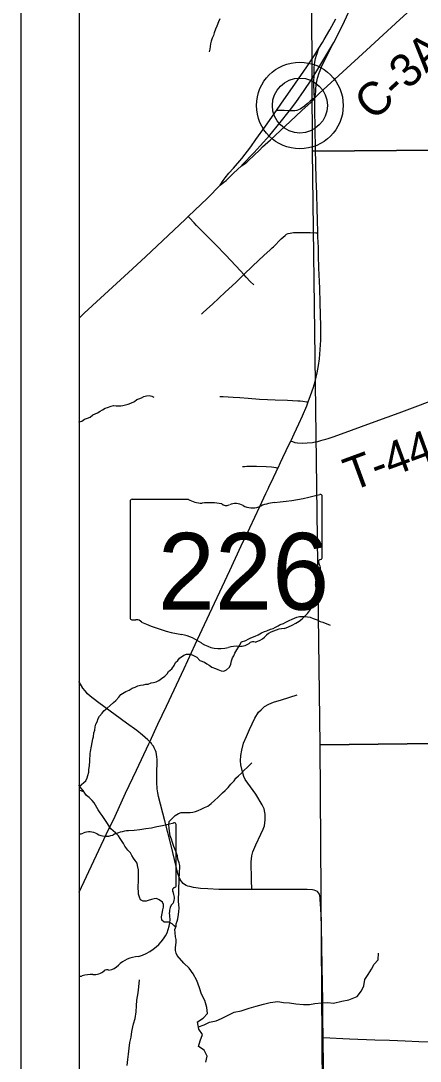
# Model space of a CAD drawing. Extents: x 0 to 34, y 0 to 22.
# Drawn here: x 17.758 to 18.444, y 10.029 to 11.815 of the extents above; entities that cross this region are included whole.
import ezdxf

# ---------------------------------------------------------------- set-up
doc = ezdxf.new("R2010")
doc.units = 0
for name, color, linetype in [('GM_X_County_Road', 7, 'Continuous'), ('GM_X_County_Road_Text', 7, 'Continuous'), ('GM_X_Interchange_Ramps', 7, 'Continuous'), ('GM_X_Major_River_Text', 7, 'Continuous'), ('GM_X_Minor_River', 7, 'Continuous'), ('GM_X_Section', 7, 'Continuous'), ('GM_X_State_Route', 7, 'Continuous'), ('GM_X_State_Shield', 7, 'Continuous'), ('GM_X_Township_Road', 7, 'Continuous'), ('GM_X_Township_Road_Text', 7, 'Continuous'), ('GM_X_Unincorporated', 7, 'Continuous'), ('GM_X_Unincorporated_Location', 7, 'Continuous'), ('SH_Data', 7, 'Continuous')]:
    doc.layers.add(name, color=color, linetype=linetype)

msp = doc.modelspace()

# ---------------------------------------------------------------- linework, layer by layer
at = {"layer": 'GM_X_County_Road'}
msp.add_lwpolyline([(18.2625, 11.683), (18.2699, 11.6903), (18.3514, 11.7649), (18.4086, 11.8174), (18.4384, 11.8446), (18.5022, 11.9035), (18.5117, 11.9129), (18.5242, 11.9253), (18.5401, 11.9425), (18.5514, 11.9551), (18.6473, 12.061), (18.7036, 12.1231), (18.7171, 12.1378)], dxfattribs=at)
at = {"layer": 'GM_X_Interchange_Ramps'}
for points in [[(18.1365, 11.5663), (18.1411, 11.5689), (18.1438, 11.571), (18.1457, 11.5726), (18.1481, 11.5749), (18.1684, 11.5939), (18.173, 11.5986), (18.1866, 11.611), (18.2202, 11.6425), (18.2404, 11.6614), (18.2564, 11.6754), (18.2587, 11.6776), (18.2602, 11.6795), (18.2625, 11.683)], [(18.2625, 11.683), (18.2581, 11.6801), (18.2548, 11.6773), (18.2494, 11.6729), (18.2449, 11.6688), (18.2425, 11.6669), (18.24, 11.6651), (18.2373, 11.6637), (18.2345, 11.6624), (18.2315, 11.6615), (18.2285, 11.6609), (18.2255, 11.6607), (18.2194, 11.6609), (18.2102, 11.6614), (18.2039, 11.6615), (18.1967, 11.6613)]]:
    msp.add_lwpolyline(points, dxfattribs=at)
at = {"layer": 'GM_X_Major_River_Text'}
msp.add_line((17.8579, 10.4195), (17.8579, 10.1742), dxfattribs=at)
msp.add_lwpolyline([(18.0245, 10.3301), (18.0245, 10.3301), (18.0245, 10.3301), (18.0245, 10.435)], dxfattribs=at)
for centre, major_axis, start_param, end_param in [((17.9071, 10.7027), (0.3495, 0), 4.814394, 5.042369), ((18.0208, 10.4352), (0.00367, 0), 6.197627, 7.989034), ((17.8601, 10.4278), (0.0107, 0), 4.502603, 5.185415), ((17.8758, 10.4047), (0.0222, 0), 0.950623, 2.079405), ((17.9045, 10.4364), (0.0267, 0), 4.08156, 5.145723), ((17.9517, 10.3687), (0.0703, 0), 1.699012, 2.107814), ((18.0237, 10.3224), (0.00568, 0), 1.883978, 3.671073), ((18.0206, 10.3297), (0.00393, 0), 5.05454, 6.418171), ((17.9875, 10.3092), (0.0341, 0), 5.934695, 6.695948), ((18.0376, 10.2863), (0.0248, 0), 2.387724, 3.262537), ((17.9267, 10.273), (0.0874, 0), 5.101753, 6.440018), ((17.9635, 10.1701), (0.0479, 0), 1.647645, 2.488434), ((17.8819, 10.1987), (0.0267, 0), 4.691044, 5.507374), ((17.9061, 10.1794), (0.00752, 0), 1.147584, 2.315152), ((17.9029, 10.2069), (0.0282, 0), 4.937069, 5.64225), ((17.8493, 10.2137), (0.0501, 0), 4.884715, 4.996735), ((17.8783, 10.1445), (0.0412, 0), 1.495662, 1.94098)]:
    msp.add_ellipse(centre, major_axis=major_axis, ratio=0.8, start_param=start_param, end_param=end_param, dxfattribs=at)
at = {"layer": 'GM_X_Minor_River'}
msp.add_line((17.8661, 10.4914), (17.8579, 10.4943), dxfattribs=at)
for points in [[(18.0993, 11.8187), (18.0974, 11.8137), (18.0945, 11.8061), (18.0919, 11.8011), (18.0901, 11.7946), (18.0886, 11.7901), (18.0864, 11.7855), (18.0849, 11.7805), (18.0838, 11.7756), (18.0828, 11.7714), (18.0824, 11.7664), (18.0814, 11.7619)], [(17.8579, 11.1263), (17.858, 11.1264), (17.8626, 11.128), (17.8675, 11.1311), (17.8724, 11.1327), (17.8769, 11.1346), (17.8818, 11.1389), (17.8898, 11.142), (17.8943, 11.1447), (17.8981, 11.1471), (17.903, 11.1498), (17.9068, 11.1514), (17.9128, 11.1537), (17.917, 11.1546), (17.9215, 11.1542), (17.9295, 11.1543), (17.9333, 11.1548), (17.9375, 11.1556), (17.942, 11.1568), (17.947, 11.1584), (17.953, 11.1615), (17.9568, 11.165), (17.9606, 11.1661), (17.9651, 11.1681), (17.9693, 11.1701), (17.9738, 11.1713), (17.9784, 11.1717), (17.9826, 11.1706), (17.9864, 11.1692)], [(17.8589, 10.5012), (17.8698, 10.5101), (17.8717, 10.515), (17.8731, 10.5192), (17.8746, 10.5249), (17.8749, 10.5295), (17.8756, 10.536), (17.8762, 10.5447), (17.8768, 10.5569), (17.8775, 10.5607), (17.8793, 10.5694), (17.8814, 10.582), (17.8825, 10.5858), (17.8832, 10.5923), (17.885, 10.5972), (17.8854, 10.603), (17.8868, 10.6075), (17.8891, 10.6114), (17.8909, 10.6171), (17.8931, 10.6213), (17.8976, 10.6263), (17.9006, 10.6305), (17.9062, 10.6351), (17.9111, 10.6394), (17.9168, 10.6444), (17.9209, 10.6482), (17.9261, 10.654), (17.9295, 10.6582), (17.9382, 10.6633), (17.9439, 10.6656), (17.9492, 10.6691), (17.9545, 10.6707), (17.959, 10.6731), (17.9635, 10.6746), (17.9688, 10.6751), (17.9726, 10.6759), (17.9768, 10.6763), (17.9817, 10.6783), (17.9855, 10.6787), (17.9905, 10.6799), (17.995, 10.6823), (17.9995, 10.6861), (18.0052, 10.6896), (18.0089, 10.6939), (18.0115, 10.6977), (18.0172, 10.7023), (18.0209, 10.7081), (18.0235, 10.7131), (18.0276, 10.7169), (18.0302, 10.7207), (18.0378, 10.7258), (18.0423, 10.7274), (18.0484, 10.7274), (18.0522, 10.7264), (18.0603, 10.7223), (18.0653, 10.717), (18.0733, 10.7137), (18.0772, 10.7111), (18.081, 10.7089), (18.0856, 10.7055), (18.0921, 10.7033), (18.0963, 10.7015), (18.1016, 10.6993), (18.1066, 10.6986), (18.1108, 10.7005), (18.116, 10.7052), (18.1186, 10.7105), (18.1197, 10.7162), (18.1215, 10.7212), (18.1234, 10.725), (18.1252, 10.7292), (18.1289, 10.735), (18.1315, 10.7399), (18.1338, 10.7438), (18.1368, 10.7488), (18.1443, 10.7511), (18.1485, 10.7535), (18.153, 10.7558), (18.1602, 10.7586), (18.1655, 10.7609), (18.1712, 10.764), (18.1765, 10.7664), (18.1802, 10.7679), (18.1863, 10.7703), (18.1912, 10.7719), (18.1954, 10.7738), (18.1995, 10.7762), (18.2033, 10.7785), (18.209, 10.7801), (18.2128, 10.7824), (18.2188, 10.7852), (18.2237, 10.7879), (18.2275, 10.7895), (18.2317, 10.7914), (18.2362, 10.7922), (18.2461, 10.7924), (18.2499, 10.7917), (18.2549, 10.791), (18.2598, 10.7888), (18.2667, 10.7866), (18.2717, 10.7836)], [(18.2717, 10.7836), (18.2763, 10.7825), (18.2805, 10.7807), (18.2851, 10.7792), (18.2889, 10.7774)], [(18.0265, 10.2103), (18.0247, 10.2139), (18.0235, 10.2185), (18.0234, 10.2234), (18.0241, 10.2284), (18.0244, 10.2325), (18.0244, 10.2379), (18.0235, 10.2424), (18.0231, 10.2492), (18.0226, 10.2549), (18.0244, 10.2603), (18.0248, 10.2645), (18.0266, 10.269), (18.0277, 10.2732), (18.0287, 10.2805), (18.0294, 10.2858), (18.0297, 10.2915), (18.0293, 10.2979), (18.0288, 10.3029), (18.0288, 10.309), (18.029, 10.3166), (18.0293, 10.3276), (18.0295, 10.3359), (18.0298, 10.3435), (18.0301, 10.3492), (18.0304, 10.3546), (18.0308, 10.3603), (18.0307, 10.3648), (18.0299, 10.3694), (18.0275, 10.3758), (18.0267, 10.3811), (18.0235, 10.3906), (18.0208, 10.3974), (18.0184, 10.4042), (18.0168, 10.4098), (18.0144, 10.4159), (18.0136, 10.4197), (18.0132, 10.4238), (18.0127, 10.4288), (18.0123, 10.4345), (18.0126, 10.4402), (18.0175, 10.4456), (18.0227, 10.4506), (18.0284, 10.4541), (18.0333, 10.456), (18.0413, 10.4557), (18.0485, 10.4558), (18.0535, 10.4563), (18.0576, 10.4575), (18.0622, 10.4591), (18.0675, 10.4614), (18.0735, 10.4642), (18.0788, 10.4669), (18.0848, 10.4711), (18.0905, 10.4762), (18.0965, 10.4823), (18.1002, 10.4854), (18.1044, 10.4893), (18.1089, 10.4935), (18.1138, 10.4989), (18.1183, 10.5043), (18.1239, 10.5104), (18.1269, 10.5146), (18.1314, 10.5189), (18.1366, 10.5235), (18.1415, 10.5285), (18.1464, 10.5331), (18.1509, 10.5377), (18.1547, 10.5412)], [(18.0239, 10.2586), (18.0214, 10.2614), (18.0175, 10.2644), (18.0126, 10.2673), (18.0084, 10.2677), (18.0038, 10.2672), (18, 10.271), (17.9995, 10.2767), (18.0006, 10.2824), (18.002, 10.2888), (18.0027, 10.2934), (18.003, 10.298), (18.0011, 10.3017), (17.9953, 10.3059), (17.9911, 10.3081), (17.9869, 10.3073), (17.982, 10.3064), (17.9767, 10.3048), (17.9729, 10.3037), (17.968, 10.3036), (17.9634, 10.3058), (17.9614, 10.3103), (17.9602, 10.3153), (17.9598, 10.3202), (17.9593, 10.3255), (17.9596, 10.3301), (17.9599, 10.3361), (17.9598, 10.3479), (17.9597, 10.3574), (17.9584, 10.365), (17.9576, 10.3688), (17.9541, 10.3733), (17.9514, 10.3774), (17.9483, 10.382), (17.9464, 10.3865), (17.9417, 10.391), (17.9367, 10.3978), (17.934, 10.4023), (17.932, 10.406), (17.9285, 10.4113), (17.9258, 10.4158), (17.9204, 10.4207), (17.9166, 10.4245), (17.9127, 10.4278), (17.9093, 10.4323), (17.9054, 10.4387), (17.8976, 10.4508), (17.8941, 10.4553), (17.8906, 10.4606), (17.886, 10.4681), (17.8836, 10.4723), (17.8805, 10.4764), (17.8751, 10.4816), (17.8709, 10.485), (17.8678, 10.4891), (17.8647, 10.4933), (17.8612, 10.4982), (17.8581, 10.5023), (17.8579, 10.5027)], [(18.0775, 10.121), (18.0737, 10.1327), (18.0681, 10.1438), (18.0647, 10.1544), (18.0602, 10.167), (18.0539, 10.1788), (18.0467, 10.1887), (18.0377, 10.1971), (18.0265, 10.2103)], [(18.0629, 10.0879), (18.0724, 10.0914), (18.0819, 10.0955), (18.0933, 10.0981), (18.1027, 10.1019), (18.1114, 10.1068), (18.1243, 10.1128), (18.1361, 10.1154), (18.1497, 10.1195), (18.1622, 10.1232), (18.1743, 10.1266), (18.186, 10.1295), (18.1993, 10.131), (18.2087, 10.1294), (18.2189, 10.129), (18.2299, 10.1274), (18.2431, 10.1262), (18.2533, 10.1262), (18.2628, 10.1277), (18.2749, 10.1291), (18.2847, 10.1294), (18.2945, 10.1286), (18.3089, 10.1316), (18.321, 10.1342), (18.3354, 10.1398), (18.3426, 10.1493), (18.3465, 10.158), (18.3484, 10.169), (18.3541, 10.1773), (18.3598, 10.1868), (18.3648, 10.1955), (18.3712, 10.203), (18.372, 10.214)], [(17.9406, 10.0211), (17.9418, 10.0313), (17.9425, 10.0408), (17.9441, 10.051), (17.9453, 10.0605), (17.9472, 10.07), (17.9487, 10.0795), (17.9511, 10.0927), (17.9545, 10.1022), (17.9557, 10.1132), (17.9565, 10.1238), (17.9573, 10.1333), (17.9592, 10.1458), (17.9604, 10.1564), (17.9616, 10.1686)], [(18.0756, 10.0269), (18.0779, 10.0375), (18.0726, 10.0478), (18.0628, 10.0539), (18.0659, 10.0634), (18.0697, 10.0743), (18.0637, 10.0835), (18.0615, 10.096), (18.071, 10.1024), (18.0786, 10.1103), (18.0775, 10.121)]]:
    msp.add_lwpolyline(points, dxfattribs=at)
at = {"layer": 'GM_X_Section'}
for points in [[(18.2539, 12.6075), (19.256, 12.6012), (19.2699, 11.5992), (18.2587, 11.5914)], [(19.2699, 11.5992), (19.2682, 10.5835), (18.2719, 10.572), (18.2587, 11.5914)], [(18.2719, 10.572), (19.2682, 10.5835), (19.2682, 10.2871), (19.2823, 9.5962), (18.8511, 9.5674), (18.2785, 9.5574)]]:
    msp.add_lwpolyline(points, close=True, dxfattribs=at)
at = {"layer": 'GM_X_State_Route'}
for points in [[(18.2919, 11.7723), (18.2952, 11.7783), (18.3039, 11.7948), (18.3134, 11.8147), (18.3234, 11.8359), (18.329, 11.8487), (18.3347, 11.8617), (18.3476, 11.8956), (18.3633, 11.9362), (18.3748, 11.9663), (18.392, 12.0089), (18.3944, 12.0148), (18.4157, 12.0701), (18.4506, 12.1598), (18.4686, 12.2061), (18.4736, 12.2191), (18.4793, 12.234), (18.4858, 12.251), (18.4879, 12.2563)], [(18.2787, 11.7834), (18.2882, 11.7998), (18.2987, 11.8189)], [(18.0999, 11.5331), (18.1055, 11.5411), (18.1089, 11.5459), (18.1152, 11.5534), (18.1228, 11.5621), (18.1372, 11.5791), (18.1526, 11.5987), (18.1616, 11.6114), (18.1778, 11.6342), (18.1967, 11.6613), (18.2045, 11.6724), (18.2296, 11.708), (18.249, 11.7362), (18.2627, 11.757), (18.2694, 11.768), (18.2757, 11.7783), (18.2787, 11.7834)], [(18.2625, 11.683), (18.2619, 11.6856), (18.2616, 11.688), (18.2612, 11.7103), (18.2613, 11.7221), (18.2613, 11.7227), (18.2618, 11.735), (18.2628, 11.7443), (18.2639, 11.7504), (18.2656, 11.7565), (18.2666, 11.7594), (18.2694, 11.768)], [(18.2613, 11.7221), (18.2659, 11.7294), (18.2919, 11.7723)], [(18.2625, 11.683), (18.2633, 11.686), (18.2636, 11.6889), (18.2643, 11.6942), (18.2646, 11.6986), (18.2652, 11.7047), (18.2661, 11.7109), (18.2675, 11.7169), (18.2702, 11.7258), (18.2707, 11.7272), (18.2754, 11.7392), (18.279, 11.7464), (18.2832, 11.7544), (18.2919, 11.7723)], [(18.0999, 11.5331), (18.1065, 11.5383), (18.1103, 11.5413), (18.1163, 11.5468), (18.1233, 11.5536), (18.1365, 11.5663), (18.1376, 11.5674), (18.1583, 11.589), (18.1689, 11.6003), (18.1853, 11.619), (18.2033, 11.6405), (18.2188, 11.66), (18.2194, 11.6609), (18.2299, 11.675), (18.2441, 11.6954), (18.2561, 11.7136), (18.2613, 11.7221)], [(18.1918, 11.0311), (18.1962, 11.0407), (18.1993, 11.0472), (18.1996, 11.0479), (18.204, 11.057), (18.2078, 11.0651), (18.2135, 11.0772), (18.2187, 11.0881), (18.2213, 11.0934), (18.2219, 11.0948), (18.227, 11.1058), (18.2351, 11.1232), (18.2413, 11.137), (18.2487, 11.1541), (18.2513, 11.1607), (18.2555, 11.1717), (18.2602, 11.1862), (18.263, 11.1957), (18.2667, 11.211), (18.269, 11.2232), (18.2704, 11.235), (18.2721, 11.2511), (18.2728, 11.2668), (18.2728, 11.2911), (18.2718, 11.3307), (18.271, 11.3564), (18.2698, 11.3906), (18.2688, 11.4124), (18.2687, 11.4261), (18.268, 11.4442), (18.2678, 11.4513), (18.2671, 11.474), (18.2665, 11.4919), (18.2661, 11.5179), (18.2652, 11.544), (18.264, 11.5955), (18.2631, 11.6297), (18.2627, 11.6639), (18.2625, 11.683)], [(17.8579, 11.3047), (17.8669, 11.313), (17.8947, 11.3387), (17.9495, 11.3894), (17.9723, 11.4104), (18.0401, 11.4743), (18.0452, 11.4792), (18.0782, 11.5109), (18.0999, 11.5331)], [(17.8579, 10.3189), (17.9047, 10.4181), (17.9197, 10.4497), (17.9377, 10.4892), (17.9563, 10.5286), (17.9775, 10.5735), (17.9792, 10.5772), (17.993, 10.6074), (18.0078, 10.6382), (18.0381, 10.7032), (18.0572, 10.7444), (18.0732, 10.7788), (18.1168, 10.8715), (18.1364, 10.9138), (18.1512, 10.9445), (18.1683, 10.9812), (18.1788, 11.0034), (18.1826, 11.0116), (18.185, 11.017), (18.1893, 11.0259), (18.1918, 11.0311)]]:
    msp.add_lwpolyline(points, dxfattribs=at)
at = {"layer": 'GM_X_State_Shield'}
for p, q in [((17.9458, 10.99), (17.9458, 10.7899)), ((18.0455, 10.9935), (17.949, 10.9935)), ((18.2753, 10.8937), (18.2753, 10.9984)), ((18.2753, 10.8938), (18.2753, 10.8937))]:
    msp.add_line(p, q, dxfattribs=at)
for centre, major_axis, start_param, end_param in [((17.9495, 10.9905), (0.00382, 0), 1.712693, 3.28349), ((18.0685, 11.0167), (0.037, 0), 4.042523, 4.731795), ((18.0808, 10.8811), (0.133, 0), 1.404758, 1.657858), ((18.2025, 10.9323), (0.0703, 0), 1.699011, 2.107814), ((18.1579, 11.2663), (0.3495, 0), 4.814394, 5.042369), ((18.2717, 10.9989), (0.00367, 0), 6.141152, 7.989035), ((18.111, 10.9915), (0.0107, 0), 3.836095, 5.185415), ((18.1267, 10.9684), (0.0222, 0), 0.950623, 2.079405), ((18.1553, 11.0001), (0.0267, 0), 4.081561, 5.145723), ((18.2745, 10.8861), (0.00568, 0), 1.883978, 3.671073), ((18.2384, 10.8728), (0.0341, 0), 5.934695, 6.695948), ((18.2714, 10.8933), (0.00393, 0), 5.05454, 6.418171), ((18.2885, 10.8499), (0.0248, 0), 2.387724, 3.262537), ((18.1775, 10.8366), (0.0874, 0), 5.101752, 6.440018), ((17.9496, 10.7895), (0.00385, 0), 3.00124, 4.508301), ((17.9501, 10.8099), (0.0294, 0), 4.665946, 4.897461), ((17.9562, 10.7784), (0.0106, 0), 0.519207, 1.627899), ((18.09, 10.9582), (0.2524, 0), 4.195997, 4.488961), ((18.0147, 10.7), (0.079, 0), 0.823519, 1.323587), ((18.1537, 10.7705), (0.0282, 0), 4.937069, 5.64225), ((18.2144, 10.7337), (0.0479, 0), 1.647645, 2.488434), ((18.1001, 10.7774), (0.0501, 0), 4.026481, 4.996735), ((18.1291, 10.7082), (0.0412, 0), 1.495662, 1.94098), ((18.1328, 10.7624), (0.0267, 0), 4.691044, 5.507374), ((18.1569, 10.743), (0.00752, 0), 1.147584, 2.315152)]:
    msp.add_ellipse(centre, major_axis=major_axis, ratio=0.8, start_param=start_param, end_param=end_param, dxfattribs=at)
at = {"layer": 'GM_X_Township_Road'}
for points in [[(18.1578, 11.3616), (18.1514, 11.3678), (18.145, 11.3748), (18.1408, 11.3794), (18.1348, 11.386), (18.1096, 11.4126), (18.0921, 11.4312), (18.0706, 11.4529), (18.0596, 11.4636), (18.0553, 11.4681), (18.0474, 11.4767), (18.0452, 11.4792)], [(18.068, 11.3116), (18.0704, 11.3137), (18.0773, 11.3201), (18.0869, 11.3289), (18.1089, 11.3492), (18.127, 11.366), (18.1408, 11.3794), (18.1556, 11.3939), (18.1759, 11.4126), (18.1853, 11.4213), (18.1897, 11.4253), (18.1919, 11.4274), (18.2049, 11.4406), (18.2118, 11.4468), (18.2143, 11.4486), (18.2171, 11.4499), (18.2201, 11.4508), (18.2231, 11.4513), (18.2262, 11.4515), (18.2323, 11.4516), (18.2478, 11.4517), (18.2545, 11.4516), (18.2642, 11.4514), (18.2678, 11.4513)], [(18.2213, 11.0934), (18.2243, 11.0926), (18.2284, 11.0914), (18.2327, 11.0908), (18.2409, 11.0901), (18.2493, 11.0904), (18.2585, 11.0914), (18.2631, 11.0921), (18.2677, 11.0931), (18.273, 11.0944), (18.2769, 11.0955), (18.2816, 11.0968), (18.2857, 11.0982), (18.2939, 11.101), (18.3019, 11.1039), (18.3663, 11.1273), (18.4074, 11.1421), (18.4395, 11.1542), (18.4774, 11.1683), (18.4979, 11.1757), (18.5243, 11.1853), (18.5564, 11.1972), (18.5739, 11.2038), (18.5982, 11.214)], [(18.0995, 11.1702), (18.1051, 11.17), (18.1226, 11.169), (18.1339, 11.1685), (18.1483, 11.1673), (18.1679, 11.1658), (18.1816, 11.1649), (18.1947, 11.1645), (18.2159, 11.1639), (18.2244, 11.1634), (18.2333, 11.1628), (18.2375, 11.1624), (18.2418, 11.1621), (18.2482, 11.1612), (18.2513, 11.1607)], [(18.1383, 11.0497), (18.1419, 11.0499), (18.1462, 11.0502), (18.1492, 11.0505), (18.1539, 11.0507), (18.158, 11.0507), (18.1628, 11.0507), (18.1794, 11.05), (18.1885, 11.0495), (18.1924, 11.0489), (18.1955, 11.0482), (18.1993, 11.0472)], [(17.9792, 10.5772), (17.9758, 10.5804), (17.9666, 10.5886), (17.9571, 10.5964), (17.9396, 10.6092), (17.8919, 10.644), (17.8819, 10.6514), (17.8771, 10.6554), (17.8725, 10.6597), (17.8683, 10.6644), (17.8646, 10.6695), (17.8581, 10.6802), (17.8579, 10.6806)], [(18.1544, 10.3233), (18.1538, 10.3403), (18.1531, 10.3708), (18.1538, 10.3761), (18.1546, 10.3814), (18.1564, 10.3882), (18.1613, 10.4004), (18.1699, 10.4187), (18.1741, 10.4271), (18.1761, 10.4331), (18.1769, 10.4381), (18.1776, 10.4432), (18.1776, 10.4485), (18.1774, 10.4529), (18.1767, 10.456), (18.1756, 10.462), (18.1725, 10.4691), (18.1615, 10.487), (18.1429, 10.5126), (18.1409, 10.5176), (18.1379, 10.5276), (18.1356, 10.5377), (18.135, 10.5444), (18.1356, 10.5539), (18.1372, 10.5627), (18.1401, 10.5748), (18.1451, 10.5861), (18.1504, 10.598), (18.1595, 10.6175), (18.1661, 10.6278), (18.1703, 10.632), (18.1765, 10.638), (18.1836, 10.6418), (18.1915, 10.6453), (18.2052, 10.6495), (18.2321, 10.6579)], [(18.2769, 10.0693), (18.2764, 10.1019), (18.2763, 10.133), (18.276, 10.1609), (18.2755, 10.1919), (18.2747, 10.226), (18.274, 10.2601), (18.2734, 10.2787), (18.2728, 10.2911), (18.2721, 10.3066), (18.2718, 10.3096), (18.2712, 10.3125), (18.2704, 10.3153), (18.2689, 10.3178), (18.267, 10.3199), (18.2645, 10.3215), (18.2617, 10.3225), (18.2588, 10.3231), (18.2496, 10.3236), (18.2342, 10.3236), (18.2031, 10.3234), (18.1659, 10.3233), (18.1544, 10.3233), (18.1287, 10.3234), (18.0976, 10.3238), (18.079, 10.3246), (18.0666, 10.3255), (18.0541, 10.3271), (18.048, 10.3284), (18.0449, 10.3294), (18.042, 10.3306), (18.0392, 10.3322), (18.0366, 10.3341), (18.0344, 10.3365), (18.0325, 10.3391), (18.0309, 10.3419), (18.0296, 10.3448), (18.0277, 10.3508), (18.0217, 10.375), (18.0158, 10.3991), (18.0049, 10.4412), (17.9944, 10.4834), (17.9932, 10.4898), (17.9926, 10.493), (17.9922, 10.4961), (17.9918, 10.4995), (17.9914, 10.505), (17.9912, 10.5109), (17.9913, 10.5257), (17.9919, 10.541), (17.9919, 10.5467), (17.9917, 10.5513), (17.9911, 10.5556), (17.9903, 10.5592), (17.9891, 10.5624), (17.9881, 10.5644), (17.987, 10.567), (17.9855, 10.5694), (17.9836, 10.572), (17.9822, 10.574), (17.9802, 10.5762), (17.9792, 10.5772)], [(18.2771, 9.322), (18.2772, 9.3272), (18.2781, 9.3769), (18.2789, 9.4141), (18.2793, 9.439), (18.2795, 9.4638), (18.2797, 9.4886), (18.2798, 9.5259), (18.2802, 9.5943), (18.2801, 9.6409), (18.2796, 9.6843), (18.2793, 9.7123), (18.2792, 9.7558), (18.2791, 9.7931), (18.2788, 9.8334), (18.2782, 9.8956), (18.2783, 9.9422), (18.2778, 9.9763), (18.2773, 10.0291), (18.2769, 10.0571), (18.2769, 10.0693)], [(18.2769, 10.0693), (18.3223, 10.0673), (18.3658, 10.0656), (18.391, 10.0646), (18.4047, 10.064), (18.4178, 10.0635), (18.4412, 10.0627), (18.4594, 10.062), (18.4812, 10.0612)]]:
    msp.add_lwpolyline(points, dxfattribs=at)
at = {"layer": 'GM_X_Unincorporated'}
for radius in [0.0744, 0.0472]:
    msp.add_circle((18.237, 11.6698), radius, dxfattribs=at)
at = {"layer": 'GM_X_Unincorporated_Location'}
msp.add_line((18.237, 11.6698), (18.237, 11.6698), dxfattribs=at)
at = {"layer": 'SH_Data'}
for p, q in [((17.7579, 16.0775), (17.7579, 9.0775)), ((17.8579, 15.9775), (17.8579, 9.1775))]:
    msp.add_line(p, q, dxfattribs=at)

# ---------------------------------------------------------------- texts
at = {"layer": 'GM_X_County_Road_Text'}
msp.add_text('C-3A', height=0.05682, rotation=42.3778, dxfattribs=at).set_placement((18.3631, 11.6418))
at = {"layer": 'GM_X_State_Shield'}
msp.add_text('226', height=0.13184, dxfattribs=at).set_placement((17.9932, 10.804))
at = {"layer": 'GM_X_Township_Road_Text'}
msp.add_text('T-446', height=0.05682, rotation=20.1972, dxfattribs=at).set_placement((18.3256, 11.0072))

doc.saveas('drawing.dxf')
